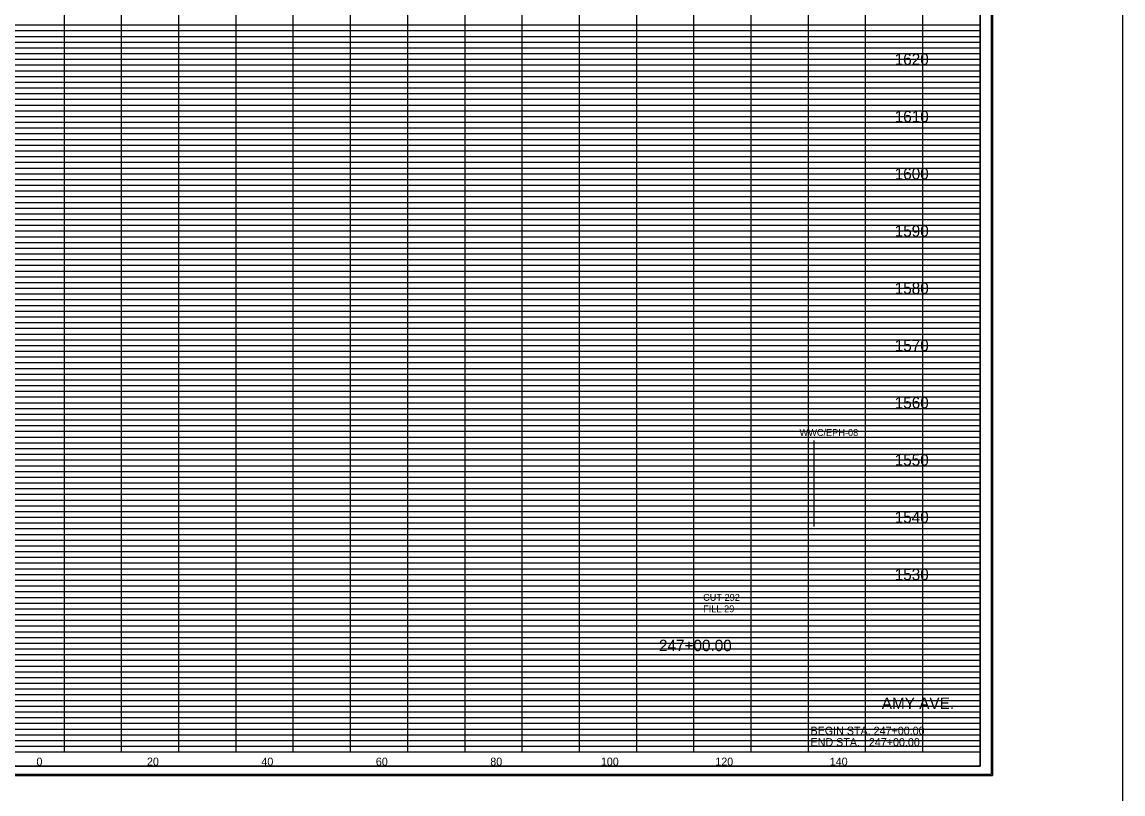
# Model space of a CAD drawing. Extents: x 955 to 1375, y 1248 to 3657.
# Drawn here: x 1152.6 to 1345, y 2072.7 to 2207.5 of the extents above; entities that cross this region are included whole.
import ezdxf

# ---------------------------------------------------------------- set-up
doc = ezdxf.new("R2010")
doc.units = 0
for name, color, linetype in [('DESIGN - SHEET - Corner Text', 7, 'Continuous'), ('DESIGN - SHEET - Light Grid', 7, 'Continuous'), ('DESIGN - SHEET - Linework', 7, 'Continuous'), ('DESIGN - SHEET - Plot Shape', 7, 'Continuous'), ('DESIGN - TYPICAL - Text', 7, 'Continuous'), ('DESIGN - UTILITIES - Cable (Overhead) with Text', 7, 'Continuous'), ('SURVEY - NON-TRANSPORTATION - Features', 7, 'Continuous'), ('SURVEY - NON-TRANSPORTATION - Features Text', 7, 'Continuous')]:
    doc.layers.add(name, color=color, linetype=linetype)

# ---------------------------------------------------------------- blocks, each defined once
blk = doc.blocks.new('XSTSHT')
at = {"layer": 'DESIGN - SHEET - Light Grid'}
for p, q in [((8, 12.7), (16, 12.7)), ((16, 12.7), (24, 12.7)), ((24, 12.7), (32, 12.7)), ((8, 12.6), (16, 12.6)), ((16, 12.6), (24, 12.6)), ((24, 12.6), (32, 12.6)), ((8, 12.5), (16, 12.5)), ((8, 12.4), (16, 12.4)), ((16, 12.5), (24, 12.5)), ((16, 12.4), (24, 12.4)), ((24, 12.5), (32, 12.5)), ((24, 12.4), (32, 12.4)), ((8, 12.3), (16, 12.3)), ((8, 12.2), (16, 12.2)), ((16, 12.3), (24, 12.3)), ((16, 12.2), (24, 12.2)), ((24, 12.3), (32, 12.3)), ((24, 12.2), (32, 12.2)), ((8, 12.1), (16, 12.1)), ((16, 12.1), (24, 12.1)), ((24, 12.1), (32, 12.1)), ((8, 11.9), (16, 11.9)), ((8, 11.8), (16, 11.8)), ((16, 11.9), (24, 11.9)), ((16, 11.8), (24, 11.8)), ((24, 11.9), (32, 11.9)), ((24, 11.8), (32, 11.8)), ((8, 11.7), (16, 11.7)), ((8, 11.6), (16, 11.6)), ((16, 11.7), (24, 11.7)), ((16, 11.6), (24, 11.6)), ((24, 11.7), (32, 11.7)), ((24, 11.6), (32, 11.6)), ((8, 11.5), (16, 11.5)), ((8, 11.4), (16, 11.4)), ((16, 11.5), (24, 11.5)), ((16, 11.4), (24, 11.4)), ((24, 11.5), (32, 11.5)), ((24, 11.4), (32, 11.4)), ((8, 11.3), (16, 11.3)), ((8, 11.2), (16, 11.2)), ((16, 11.3), (24, 11.3)), ((16, 11.2), (24, 11.2)), ((24, 11.3), (32, 11.3)), ((24, 11.2), (32, 11.2)), ((8, 11.1), (16, 11.1)), ((16, 11.1), (24, 11.1)), ((24, 11.1), (32, 11.1)), ((8, 10.9), (16, 10.9)), ((8, 10.8), (16, 10.8)), ((16, 10.9), (24, 10.9)), ((16, 10.8), (24, 10.8)), ((24, 10.9), (32, 10.9)), ((24, 10.8), (32, 10.8)), ((8, 10.7), (16, 10.7)), ((8, 10.6), (16, 10.6)), ((16, 10.7), (24, 10.7)), ((16, 10.6), (24, 10.6)), ((24, 10.7), (32, 10.7)), ((24, 10.6), (32, 10.6)), ((8, 10.5), (16, 10.5)), ((8, 10.4), (16, 10.4)), ((16, 10.5), (24, 10.5)), ((16, 10.4), (24, 10.4)), ((24, 10.5), (32, 10.5)), ((24, 10.4), (32, 10.4)), ((8, 10.3), (16, 10.3)), ((8, 10.2), (16, 10.2)), ((16, 10.3), (24, 10.3)), ((16, 10.2), (24, 10.2)), ((24, 10.3), (32, 10.3)), ((24, 10.2), (32, 10.2)), ((8, 10.1), (16, 10.1)), ((16, 10.1), (24, 10.1)), ((24, 10.1), (32, 10.1)), ((8, 9.9), (16, 9.9)), ((16, 9.9), (24, 9.9)), ((24, 9.9), (32, 9.9)), ((8, 9.8), (16, 9.8)), ((8, 9.7), (16, 9.7)), ((16, 9.8), (24, 9.8)), ((16, 9.7), (24, 9.7)), ((24, 9.8), (32, 9.8)), ((24, 9.7), (32, 9.7)), ((8, 9.6), (16, 9.6)), ((8, 9.5), (16, 9.5)), ((16, 9.6), (24, 9.6)), ((16, 9.5), (24, 9.5)), ((24, 9.6), (32, 9.6)), ((24, 9.5), (32, 9.5)), ((8, 9.4), (16, 9.4)), ((8, 9.3), (16, 9.3)), ((16, 9.4), (24, 9.4)), ((16, 9.3), (24, 9.3)), ((24, 9.4), (32, 9.4)), ((24, 9.3), (32, 9.3)), ((8, 9.2), (16, 9.2)), ((8, 9.1), (16, 9.1)), ((16, 9.2), (24, 9.2)), ((16, 9.1), (24, 9.1)), ((24, 9.2), (32, 9.2)), ((24, 9.1), (32, 9.1)), ((8, 8.9), (16, 8.9)), ((16, 8.9), (24, 8.9)), ((24, 8.9), (32, 8.9)), ((8, 8.8), (16, 8.8)), ((8, 8.7), (16, 8.7)), ((16, 8.8), (24, 8.8)), ((16, 8.7), (24, 8.7)), ((24, 8.8), (32, 8.8)), ((24, 8.7), (32, 8.7)), ((8, 8.6), (16, 8.6)), ((8, 8.5), (16, 8.5)), ((16, 8.6), (24, 8.6)), ((16, 8.5), (24, 8.5)), ((24, 8.6), (32, 8.6)), ((24, 8.5), (32, 8.5)), ((8, 8.4), (16, 8.4)), ((8, 8.3), (16, 8.3)), ((16, 8.4), (24, 8.4)), ((16, 8.3), (24, 8.3)), ((24, 8.4), (32, 8.4)), ((24, 8.3), (32, 8.3)), ((8, 8.2), (16, 8.2)), ((8, 8.1), (16, 8.1)), ((16, 8.2), (24, 8.2)), ((16, 8.1), (24, 8.1)), ((24, 8.2), (32, 8.2)), ((24, 8.1), (32, 8.1)), ((8, 7.9), (16, 7.9)), ((16, 7.9), (24, 7.9)), ((24, 7.9), (32, 7.9)), ((8, 7.8), (16, 7.8)), ((8, 7.7), (16, 7.7)), ((16, 7.8), (24, 7.8)), ((16, 7.7), (24, 7.7)), ((24, 7.8), (32, 7.8)), ((24, 7.7), (32, 7.7)), ((8, 7.6), (16, 7.6)), ((16, 7.6), (24, 7.6)), ((24, 7.6), (32, 7.6)), ((8, 7.5), (16, 7.5)), ((8, 7.4), (16, 7.4)), ((16, 7.5), (24, 7.5)), ((16, 7.4), (24, 7.4)), ((24, 7.5), (32, 7.5)), ((24, 7.4), (32, 7.4)), ((8, 7.3), (16, 7.3)), ((8, 7.2), (16, 7.2)), ((16, 7.3), (24, 7.3)), ((16, 7.2), (24, 7.2)), ((24, 7.3), (32, 7.3)), ((24, 7.2), (32, 7.2)), ((8, 7.1), (16, 7.1)), ((16, 7.1), (24, 7.1)), ((24, 7.1), (32, 7.1)), ((8, 6.9), (16, 6.9)), ((8, 6.8), (16, 6.8)), ((16, 6.9), (24, 6.9)), ((16, 6.8), (24, 6.8)), ((24, 6.9), (32, 6.9)), ((24, 6.8), (32, 6.8)), ((8, 6.7), (16, 6.7)), ((8, 6.6), (16, 6.6)), ((16, 6.7), (24, 6.7)), ((16, 6.6), (24, 6.6)), ((24, 6.7), (32, 6.7)), ((24, 6.6), (32, 6.6)), ((8, 6.5), (16, 6.5)), ((8, 6.4), (16, 6.4)), ((16, 6.5), (24, 6.5)), ((16, 6.4), (24, 6.4)), ((24, 6.5), (32, 6.5)), ((24, 6.4), (32, 6.4)), ((8, 6.3), (16, 6.3)), ((8, 6.2), (16, 6.2)), ((16, 6.3), (24, 6.3)), ((16, 6.2), (24, 6.2)), ((24, 6.3), (32, 6.3)), ((24, 6.2), (32, 6.2)), ((8, 6.1), (16, 6.1)), ((16, 6.1), (24, 6.1)), ((24, 6.1), (32, 6.1)), ((8, 5.9), (16, 5.9)), ((8, 5.8), (16, 5.8)), ((16, 5.9), (24, 5.9)), ((16, 5.8), (24, 5.8)), ((24, 5.9), (32, 5.9)), ((24, 5.8), (32, 5.8)), ((8, 5.7), (16, 5.7)), ((8, 5.6), (16, 5.6)), ((16, 5.7), (24, 5.7)), ((16, 5.6), (24, 5.6)), ((24, 5.7), (32, 5.7)), ((24, 5.6), (32, 5.6)), ((8, 5.5), (16, 5.5)), ((8, 5.4), (16, 5.4)), ((16, 5.5), (24, 5.5)), ((16, 5.4), (24, 5.4)), ((24, 5.5), (32, 5.5)), ((24, 5.4), (32, 5.4)), ((8, 5.3), (16, 5.3)), ((8, 5.2), (16, 5.2)), ((16, 5.3), (24, 5.3)), ((16, 5.2), (24, 5.2)), ((24, 5.3), (32, 5.3)), ((24, 5.2), (32, 5.2)), ((8, 5.1), (16, 5.1)), ((16, 5.1), (24, 5.1)), ((24, 5.1), (32, 5.1)), ((8, 4.9), (16, 4.9)), ((16, 4.9), (24, 4.9)), ((24, 4.9), (32, 4.9)), ((8, 4.8), (16, 4.8)), ((8, 4.7), (16, 4.7)), ((16, 4.8), (24, 4.8)), ((16, 4.7), (24, 4.7)), ((24, 4.8), (32, 4.8)), ((24, 4.7), (32, 4.7)), ((8, 4.6), (16, 4.6)), ((8, 4.5), (16, 4.5)), ((16, 4.6), (24, 4.6)), ((16, 4.5), (24, 4.5)), ((24, 4.6), (32, 4.6)), ((24, 4.5), (32, 4.5)), ((8, 4.4), (16, 4.4)), ((8, 4.3), (16, 4.3)), ((16, 4.4), (24, 4.4)), ((16, 4.3), (24, 4.3)), ((24, 4.4), (32, 4.4)), ((24, 4.3), (32, 4.3)), ((8, 4.2), (16, 4.2)), ((8, 4.1), (16, 4.1)), ((16, 4.2), (24, 4.2)), ((16, 4.1), (24, 4.1)), ((24, 4.2), (32, 4.2)), ((24, 4.1), (32, 4.1)), ((8, 3.9), (16, 3.9)), ((16, 3.9), (24, 3.9)), ((24, 3.9), (32, 3.9)), ((8, 3.8), (16, 3.8)), ((8, 3.7), (16, 3.7)), ((16, 3.8), (24, 3.8)), ((16, 3.7), (24, 3.7)), ((24, 3.8), (32, 3.8)), ((24, 3.7), (32, 3.7)), ((8, 3.6), (16, 3.6)), ((8, 3.5), (16, 3.5)), ((16, 3.6), (24, 3.6)), ((16, 3.5), (24, 3.5)), ((24, 3.6), (32, 3.6)), ((24, 3.5), (32, 3.5)), ((8, 3.4), (16, 3.4)), ((8, 3.3), (16, 3.3)), ((16, 3.4), (24, 3.4)), ((16, 3.3), (24, 3.3)), ((24, 3.4), (32, 3.4)), ((24, 3.3), (32, 3.3)), ((8, 3.2), (16, 3.2)), ((8, 3.1), (16, 3.1)), ((16, 3.2), (24, 3.2)), ((16, 3.1), (24, 3.1)), ((24, 3.2), (32, 3.2)), ((24, 3.1), (32, 3.1)), ((8, 2.9), (16, 2.9)), ((16, 2.9), (24, 2.9)), ((24, 2.9), (32, 2.9)), ((8, 2.8), (16, 2.8)), ((8, 2.7), (16, 2.7)), ((16, 2.8), (24, 2.8)), ((16, 2.7), (24, 2.7)), ((24, 2.8), (32, 2.8)), ((24, 2.7), (32, 2.7)), ((8, 2.6), (16, 2.6)), ((16, 2.6), (24, 2.6)), ((24, 2.6), (32, 2.6)), ((8, 2.5), (16, 2.5)), ((8, 2.4), (16, 2.4)), ((16, 2.5), (24, 2.5)), ((16, 2.4), (24, 2.4)), ((24, 2.5), (32, 2.5)), ((24, 2.4), (32, 2.4)), ((8, 2.3), (16, 2.3)), ((8, 2.2), (16, 2.2)), ((16, 2.3), (24, 2.3)), ((16, 2.2), (24, 2.2)), ((24, 2.3), (32, 2.3)), ((24, 2.2), (32, 2.2)), ((8, 2.1), (16, 2.1)), ((16, 2.1), (24, 2.1)), ((24, 2.1), (32, 2.1)), ((8, 1.9), (16, 1.9)), ((8, 1.8), (16, 1.8)), ((16, 1.9), (24, 1.9)), ((16, 1.8), (24, 1.8)), ((24, 1.9), (32, 1.9)), ((24, 1.8), (32, 1.8)), ((8, 1.7), (16, 1.7)), ((8, 1.6), (16, 1.6)), ((16, 1.7), (24, 1.7)), ((16, 1.6), (24, 1.6)), ((24, 1.7), (32, 1.7)), ((24, 1.6), (32, 1.6)), ((8, 1.5), (16, 1.5)), ((8, 1.4), (16, 1.4)), ((16, 1.5), (24, 1.5)), ((16, 1.4), (24, 1.4)), ((24, 1.5), (32, 1.5)), ((24, 1.4), (32, 1.4)), ((8, 1.3), (16, 1.3)), ((8, 1.2), (16, 1.2)), ((16, 1.3), (24, 1.3)), ((16, 1.2), (24, 1.2)), ((24, 1.3), (32, 1.3)), ((24, 1.2), (32, 1.2)), ((8, 1.1), (16, 1.1)), ((16, 1.1), (24, 1.1)), ((24, 1.1), (32, 1.1)), ((8, 0.9), (16, 0.9)), ((8, 0.8), (16, 0.8)), ((16, 0.9), (24, 0.9)), ((16, 0.8), (24, 0.8)), ((24, 0.9), (32, 0.9)), ((24, 0.8), (32, 0.8)), ((8, 0.7), (16, 0.7)), ((8, 0.6), (16, 0.6)), ((16, 0.7), (24, 0.7)), ((16, 0.6), (24, 0.6)), ((24, 0.7), (32, 0.7)), ((24, 0.6), (32, 0.6)), ((8, 0.5), (16, 0.5)), ((8, 0.4), (16, 0.4)), ((16, 0.5), (24, 0.5)), ((16, 0.4), (24, 0.4)), ((24, 0.5), (32, 0.5)), ((24, 0.4), (32, 0.4)), ((8, 0.3), (16, 0.3)), ((8, 0.2), (16, 0.2)), ((16, 0.3), (24, 0.3)), ((16, 0.2), (24, 0.2)), ((24, 0.3), (32, 0.3)), ((24, 0.2), (32, 0.2)), ((8, 0.1), (16, 0.1)), ((16, 0.1), (24, 0.1)), ((24, 0.1), (32, 0.1))]:
    blk.add_line(p, q, dxfattribs=at)
at = {"layer": 'DESIGN - SHEET - Linework'}
for p, q in [((32.217, 21.414), (32.217, -0.414)), ((16, 0), (16, 21)), ((17, 0), (17, 21)), ((18, 0), (18, 21)), ((19, 0), (19, 21)), ((20, 0), (20, 21)), ((21, 0), (21, 21)), ((22, 0), (22, 21)), ((23, 0), (23, 21)), ((24, 0), (24, 21)), ((25, 0), (25, 21)), ((26, 0), (26, 21)), ((27, 0), (27, 21)), ((28, 0), (28, 20)), ((29, 0), (29, 20)), ((30, 0), (30, 20)), ((31, 0), (31, 20)), ((0, 12), (32, 12)), ((0, 11), (32, 11)), ((0, 10), (32, 10)), ((0, 9), (32, 9)), ((0, 8), (32, 8)), ((0, 7), (32, 7)), ((0, 6), (32, 6)), ((0, 5), (32, 5)), ((0, 4), (32, 4)), ((0, 3), (32, 3)), ((0, 2), (32, 2)), ((0, 1), (32, 1)), ((-1.823, -0.414), (32.217, -0.414))]:
    blk.add_line(p, q, dxfattribs=at)
blk.add_lwpolyline([(0, 21), (0, 0), (32, 0), (32, 21), (0, 21)], dxfattribs=at)
at = {"layer": 'DESIGN - SHEET - Plot Shape'}
for points in [[(-1.803, 21.394), (32.197, 21.394), (32.197, -0.394), (-1.803, -0.394)], [(-0.85, 21), (32, 21), (32, -0.25), (-0.85, -0.25)]]:
    blk.add_lwpolyline(points, close=True, dxfattribs=at)

msp = doc.modelspace()

# ---------------------------------------------------------------- linework, layer by layer
at = {"layer": 'DESIGN - SHEET - Plot Shape'}
msp.add_lwpolyline([(991.5, 2077.5), (1320, 2077.5), (1320, 2290), (991.5, 2290)], close=True, dxfattribs=at)
at = {"layer": 'SURVEY - NON-TRANSPORTATION - Features'}
msp.add_line((1290.99, 2119.4), (1290.99, 2134.4), dxfattribs=at)
at = {"layer": 'SURVEY - NON-TRANSPORTATION - Features Text'}
msp.add_lwpolyline([(955.41, 1505.76), (1344.98, 1505.76), (1344.98, 3398.01), (955.41, 3398.01)], close=True, dxfattribs=at)

# ---------------------------------------------------------------- block references
at = {"layer": 'DESIGN - UTILITIES - Cable (Overhead) with Text', "xscale": 10, "yscale": 10}
msp.add_blockref('XSTSHT', (1000, 2080), dxfattribs=at)

# ---------------------------------------------------------------- texts
at = {"layer": 'DESIGN - SHEET - Corner Text'}
for s, height, p in [('AMY AVE.', 2, (1302.83, 2087.5)), ('BEGIN STA. 247+00.00', 1.4, (1290.38, 2083)), ('END STA.   247+00.00', 1.4, (1290.38, 2081))]:
    msp.add_text(s, height=height, dxfattribs=at).set_placement(p)
at = {"layer": 'DESIGN - TYPICAL - Text'}
for s, height, p in [('     1620     ', 2, (1301.37, 2200)), ('     1610     ', 2, (1301.37, 2190)), ('     1600     ', 2, (1301.37, 2180)), ('     1590     ', 2, (1301.37, 2170)), ('     1580     ', 2, (1301.37, 2160)), ('     1570     ', 2, (1301.37, 2150)), ('     1560     ', 2, (1301.37, 2140)), ('     1550     ', 2, (1301.37, 2130)), ('     1540     ', 2, (1301.37, 2120)), ('     1530     ', 2, (1301.37, 2110)), ('CUT 292', 1.2, (1271.61, 2106.39)), ('FILL 29', 1.2, (1271.61, 2104.39)), ('     247+00.00     ', 2, (1260.18, 2097.6)), ('     0     ', 1.4, (1152.51, 2077.6)), ('     0     ', 1.4, (1152.51, 2077.6)), ('     20     ', 1.4, (1171.82, 2077.6)), ('     40     ', 1.4, (1191.82, 2077.6)), ('     60     ', 1.4, (1211.82, 2077.6)), ('     80     ', 1.4, (1231.82, 2077.6)), ('     100     ', 1.4, (1251.14, 2077.6)), ('     120     ', 1.4, (1271.14, 2077.6)), ('     140     ', 1.4, (1291.14, 2077.6))]:
    msp.add_text(s, height=height, dxfattribs=at).set_placement(p)
at = {"layer": 'SURVEY - NON-TRANSPORTATION - Features'}
msp.add_text('WWC/EPH-08', height=1.2, dxfattribs=at).set_placement((1288.46, 2135.19))

doc.saveas('drawing.dxf')
